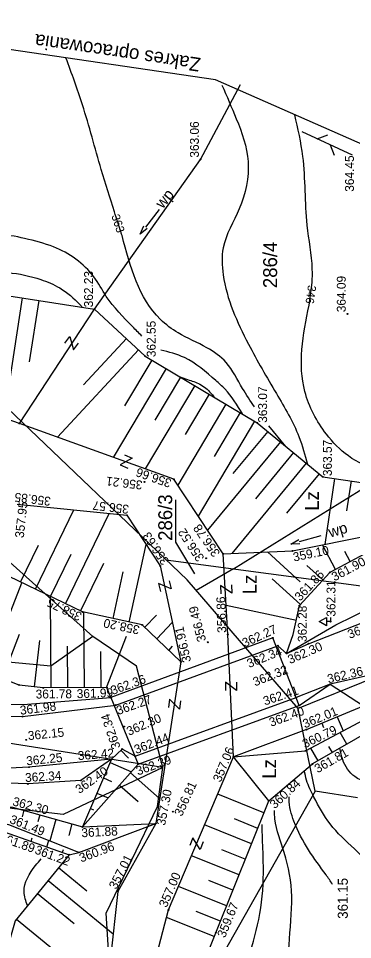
# Model space of a CAD drawing. Extents: x 4635329 to 4651863, y 5356628 to 5367582.
# Drawn here: x 4651193.1 to 4651223.2, y 5356669.9 to 5356752.8 of the extents above; entities that cross this region are included whole.
import ezdxf

# ---------------------------------------------------------------- set-up
doc = ezdxf.new("R2010")
doc.units = 0
for name, color, linetype in [('Level 1', 7, 'Continuous'), ('Level 12', 7, 'Continuous'), ('Level 20', 7, 'Continuous'), ('Level 24', 7, 'Continuous'), ('Level 29', 7, 'Continuous'), ('Level 32', 7, 'Continuous'), ('Level 36', 7, 'Continuous'), ('Level 4', 7, 'Continuous'), ('Level 44', 7, 'Continuous'), ('Level 45', 7, 'Continuous'), ('Level 46', 7, 'Continuous'), ('Level 47', 7, 'Continuous'), ('Level 48', 7, 'Continuous'), ('Level 5', 7, 'Continuous'), ('Level 50', 7, 'Continuous'), ('Level 51', 7, 'Continuous'), ('Level 53', 7, 'Continuous'), ('Level 6', 7, 'Continuous')]:
    doc.layers.add(name, color=color, linetype=linetype)

msp = doc.modelspace()

# ---------------------------------------------------------------- linework, layer by layer
at = {"layer": 'Level 1'}
for p, q in [((4651210.82, 5356747.317), (4651142.124, 5356757.357)), ((4651230.35, 5356738.707), (4651210.82, 5356747.317))]:
    msp.add_line(p, q, dxfattribs=at)
at = {"layer": 'Level 20'}
for p, q in [((4651219.185, 5356696.567), (4651225.385, 5356698.987)), ((4651201.855, 5356691.047), (4651216.435, 5356696.387)), ((4651217.225, 5356695.687), (4651219.185, 5356696.567))]:
    msp.add_line(p, q, dxfattribs=at)
for points in [[(4651122.765, 5356712.887), (4651146.685, 5356703.427), (4651159.565, 5356698.457), (4651170.205, 5356694.067), (4651178.895, 5356691.327), (4651182.663, 5356690.554), (4651185.995, 5356690.057), (4651193.465, 5356690.007), (4651201.855, 5356691.047)], [(4651201.455, 5356686.167), (4651194.035, 5356685.457), (4651185.485, 5356685.017), (4651181.21, 5356685.664), (4651178.315, 5356686.247), (4651168.145, 5356689.587), (4651157.765, 5356693.687), (4651144.895, 5356698.917), (4651120.155, 5356708.837)], [(4651311.985, 5356685.667), (4651297.855, 5356693.767), (4651287.285, 5356699.227), (4651283.015, 5356700.977), (4651280.145, 5356701.933), (4651275.335, 5356703.187), (4651271.856, 5356703.778), (4651268.065, 5356704.157), (4651257.665, 5356703.887), (4651250.625, 5356702.417), (4651229.275, 5356695.327), (4651226.835, 5356694.217), (4651221.145, 5356692.917), (4651218.085, 5356691.717)], [(4651221.145, 5356692.917), (4651224.155, 5356690.967), (4651229.698, 5356690.126), (4651238.165, 5356687.457), (4651245.645, 5356686.947), (4651253.435, 5356678.667)], [(4651203.595, 5356686.437), (4651218.085, 5356691.717)]]:
    msp.add_lwpolyline(points, dxfattribs=at)
at = {"layer": 'Level 24'}
for p, q in [((4651221.165, 5356698.557), (4651220.815, 5356698.557)), ((4651221.165, 5356698.932), (4651221.165, 5356698.557))]:
    msp.add_line(p, q, dxfattribs=at)
msp.add_lwpolyline([(4651220.815, 5356698.932), (4651220.815, 5356698.182), (4651220.165, 5356698.557)], close=True, dxfattribs=at)
at = {"layer": 'Level 29'}
msp.add_lwpolyline([(4651218.345, 5356691.007), (4651215.975, 5356697.087), (4651201.405, 5356691.717), (4651203.865, 5356685.737)], close=True, dxfattribs=at)
at = {"layer": 'Level 32'}
for p, q in [((4651223.161, 5356740.546), (4651218.621, 5356742.641)), ((4651219.983, 5356742.012), (4651220.921, 5356742.358)), ((4651221.157, 5356741.471), (4651221.503, 5356740.533))]:
    msp.add_line(p, q, dxfattribs=at)
at = {"layer": 'Level 4'}
for p, q in [((4651208.259, 5356702.31), (4651191.397, 5356718.379)), ((4651212.432, 5356703.313), (4651224.635, 5356710.859)), ((4651207.227, 5356709.519), (4651207.227, 5356705.702)), ((4651189.548, 5356706.371), (4651199.767, 5356697.217)), ((4651207.227, 5356705.702), (4651208.923, 5356702.854)), ((4651206.354, 5356704.126), (4651224.825, 5356701.657)), ((4651212.432, 5356703.313), (4651209.076, 5356701.364)), ((4651218.267, 5356690.729), (4651208.259, 5356702.31)), ((4651199.767, 5356697.217), (4651196.006, 5356694.549)), ((4651203.71, 5356694.549), (4651199.767, 5356697.217)), ((4651196.006, 5356694.549), (4651177.75, 5356696.277)), ((4651206.08, 5356685.424), (4651203.71, 5356694.549)), ((4651228.971, 5356695.066), (4651218.267, 5356690.729)), ((4651206.08, 5356685.424), (4651174.835, 5356690.307)), ((4651219.808, 5356683.279), (4651218.267, 5356690.729)), ((4651206.08, 5356685.424), (4651197.109, 5356681.204)), ((4651205.59, 5356681.906), (4651206.08, 5356685.424)), ((4651197.109, 5356681.204), (4651178.797, 5356683.326)), ((4651219.808, 5356683.279), (4651211.17, 5356668.081)), ((4651223.595, 5356682.687), (4651219.808, 5356683.279)), ((4651200.98, 5356672.325), (4651205.59, 5356681.906)), ((4651203.591, 5356632.939), (4651200.98, 5356672.325))]:
    msp.add_line(p, q, dxfattribs=at)
at = {"layer": 'Level 44'}
for centre in [(4651209.475, 5356740.157), (4651199.945, 5356726.687), (4651222.695, 5356726.247), (4651204.495, 5356722.447), (4651193.175, 5356716.387), (4651214.585, 5356716.447), (4651204.435, 5356711.127), (4651207.065, 5356711.367), (4651220.475, 5356711.587), (4651202.845, 5356708.137), (4651211.525, 5356704.647), (4651217.765, 5356704.917), (4651205.835, 5356703.577), (4651209.985, 5356704.257), (4651221.105, 5356702.987), (4651198.845, 5356699.427), (4651218.395, 5356700.007), (4651221.165, 5356698.557), (4651204.215, 5356698.267), (4651211.945, 5356697.397), (4651215.975, 5356697.087), (4651210.125, 5356696.697), (4651216.435, 5356696.387), (4651219.185, 5356696.567), (4651217.225, 5356695.687), (4651207.695, 5356694.927), (4651217.085, 5356693.927), (4651193.145, 5356692.847), (4651221.145, 5356692.917), (4651195.325, 5356692.587), (4651201.035, 5356692.627), (4651201.405, 5356691.717), (4651201.855, 5356691.047), (4651218.085, 5356691.717), (4651218.345, 5356691.007), (4651193.465, 5356690.007), (4651202.595, 5356689.107), (4651219.005, 5356688.837), (4651193.792, 5356687.909), (4651202.425, 5356687.087), (4651218.935, 5356686.927), (4651201.455, 5356686.167), (4651203.595, 5356686.437), (4651212.455, 5356686.387), (4651194.035, 5356685.457), (4651203.865, 5356685.737), (4651219.555, 5356685.747), (4651193.935, 5356683.947), (4651198.715, 5356684.257), (4651215.615, 5356682.427), (4651206.975, 5356681.447), (4651205.445, 5356680.397), (4651198.855, 5356680.077), (4651198.515, 5356677.787), (4651197.655, 5356677.577), (4651202.025, 5356674.277), (4651206.595, 5356672.607), (4651210.845, 5356670.557)]:
    msp.add_circle(centre, 0.04, dxfattribs=at)
at = {"layer": 'Level 46'}
for p, q in [((4651219.243, 5356727.032), (4651219.529, 5356729.059)), ((4651217.167, 5356714.317), (4651215.62, 5356716.158))]:
    msp.add_line(p, q, dxfattribs=at)
for points in [[(4651204.195, 5356724.252), (4651203.361, 5356725.098), (4651200.995, 5356727.826), (4651199.873, 5356729.585), (4651196.249, 5356732.275), (4651193.641, 5356733.033), (4651191.154, 5356733.306), (4651188.364, 5356732.275), (4651185.605, 5356732.093), (4651183.512, 5356732.548), (4651181.615, 5356733.242), (4651180.554, 5356740.7), (4651184.132, 5356743.489), (4651186.498, 5356745.338), (4651187.923, 5356747.43), (4651189.44, 5356750.442)], [(4651201.723, 5356735.433), (4651200.535, 5356739.239), (4651198.848, 5356745.072), (4651197.362, 5356749.284)], [(4651211.392, 5356746.839), (4651212.696, 5356743.807), (4651213.757, 5356739.957), (4651212.968, 5356735.712), (4651211.513, 5356732.196), (4651211.513, 5356729.77), (4651213.785, 5356723.537), (4651216.302, 5356719.08), (4651218.334, 5356715.2), (4651219.113, 5356712.711)], [(4651219.529, 5356729.059), (4651219.536, 5356730.286), (4651219.082, 5356734.227), (4651218.689, 5356740.425), (4651217.952, 5356744.173)], [(4651202.411, 5356733.299), (4651202.324, 5356733.569), (4651201.723, 5356735.433)], [(4651214.332, 5356717.879), (4651213.262, 5356719.537), (4651211.776, 5356721.872), (4651210.047, 5356723.206), (4651207.45, 5356724.535), (4651205.873, 5356725.748), (4651202.411, 5356733.299)], [(4651185.981, 5356729.569), (4651186.583, 5356729.429), (4651189.555, 5356729.762), (4651192.163, 5356729.944), (4651195.087, 5356729.339), (4651196.815, 5356728.581), (4651198.605, 5356727.096), (4651198.829, 5356726.859)], [(4651234.621, 5356711.14), (4651232.261, 5356711.494), (4651228.773, 5356712.252), (4651225.559, 5356712.282), (4651222.781, 5356713.461), (4651220.81, 5356715.431), (4651218.869, 5356719.251), (4651218.596, 5356723.041), (4651219.243, 5356727.032)], [(4651213.251, 5356717.24), (4651211.663, 5356719.494), (4651210.851, 5356720.247), (4651208.031, 5356722.309), (4651205.901, 5356722.997)], [(4651207.632, 5356720.582), (4651208.302, 5356720.339), (4651209.424, 5356719.915), (4651210.394, 5356719.127), (4651210.681, 5356718.769)], [(4651235.574, 5356680.782), (4651233.613, 5356682.904), (4651230.338, 5356685.268), (4651227.669, 5356685.026), (4651225.667, 5356684.177), (4651223.363, 5356684.601), (4651222.271, 5356686.117), (4651222.011, 5356687.156)], [(4651228.12, 5356672.269), (4651226.297, 5356674.945), (4651223.325, 5356678.098), (4651221.142, 5356680.341), (4651219.686, 5356682.766), (4651219.019, 5356684.282), (4651218.821, 5356685.129)], [(4651221.361, 5356674.907), (4651220.777, 5356675.758), (4651219.2, 5356678.001), (4651217.883, 5356680.579), (4651217.459, 5356682.58), (4651217.469, 5356682.777)], [(4651214.541, 5356635.926), (4651215.44, 5356637.377), (4651218.048, 5356641.682), (4651220.05, 5356646.351), (4651221.202, 5356650.595), (4651221.02, 5356654.294), (4651220.11, 5356658.417), (4651217.442, 5356667.027), (4651217.442, 5356669.452), (4651217.684, 5356673.818), (4651217.017, 5356677.759), (4651216.168, 5356680.79), (4651216.131, 5356681.56)], [(4651214.19, 5356661.051), (4651213.196, 5356664.419), (4651213.681, 5356667.815), (4651214.712, 5356671.756), (4651215.137, 5356675.94), (4651215.076, 5356678.426), (4651215.015, 5356680.305)], [(4651193.902, 5356672.991), (4651193.59, 5356674.238), (4651194.621, 5356676.602), (4651195.138, 5356677.203)]]:
    msp.add_spline(points, degree=3, dxfattribs=at)
at = {"layer": 'Level 48'}
for p, q in [((4651193.43, 5356727.693), (4651191.76, 5356716.874)), ((4651194.912, 5356727.464), (4651194.057, 5356721.921)), ((4651202.804, 5356724.023), (4651198.929, 5356719.865)), ((4651203.901, 5356723), (4651196.589, 5356715.153)), ((4651205.087, 5356722.095), (4651202.636, 5356717.974)), ((4651206.376, 5356721.328), (4651201.622, 5356713.334)), ((4651207.665, 5356720.562), (4651205.362, 5356716.688)), ((4651208.955, 5356719.795), (4651204.495, 5356712.296)), ((4651210.244, 5356719.028), (4651208.088, 5356715.403)), ((4651211.76, 5356718.127), (4651207.421, 5356710.83)), ((4651213.049, 5356717.36), (4651210.695, 5356713.402)), ((4651214.339, 5356716.594), (4651209.262, 5356708.057)), ((4651215.521, 5356715.675), (4651212.385, 5356711.875)), ((4651216.678, 5356714.72), (4651210.117, 5356706.769)), ((4651217.835, 5356713.766), (4651214.409, 5356709.614)), ((4651218.992, 5356712.811), (4651212.283, 5356704.68)), ((4651220.149, 5356711.856), (4651217.224, 5356708.312)), ((4651221.54, 5356711.43), (4651220.666, 5356705.501)), ((4651223.024, 5356711.211), (4651222.626, 5356708.513)), ((4651194.628, 5356701.462), (4651198.08, 5356708.615)), ((4651197.33, 5356700.158), (4651201.257, 5356708.296)), ((4651193.277, 5356702.114), (4651194.884, 5356705.444)), ((4651203.065, 5356698.515), (4651204.574, 5356705.5)), ((4651221.618, 5356703.257), (4651220.458, 5356705.459)), ((4651195.979, 5356700.81), (4651197.823, 5356704.633)), ((4651218.454, 5356702.127), (4651215.494, 5356704.819)), ((4651222.945, 5356703.957), (4651222.468, 5356704.862)), ((4651198.68, 5356699.506), (4651200.763, 5356703.822)), ((4651220.486, 5356702.306), (4651219.054, 5356703.608)), ((4651201.599, 5356698.832), (4651202.509, 5356703.046)), ((4651190.245, 5356693.976), (4651193.393, 5356702.058)), ((4651198.845, 5356699.427), (4651192.255, 5356702.607)), ((4651218.468, 5356700.087), (4651215.917, 5356702.407)), ((4651196.017, 5356692.592), (4651195.96, 5356700.819)), ((4651204.215, 5356698.267), (4651198.845, 5356699.427)), ((4651199.017, 5356692.613), (4651198.97, 5356699.4)), ((4651218.1, 5356698.647), (4651211.793, 5356700.014)), ((4651204.448, 5356698.043), (4651205.501, 5356699.14)), ((4651207.695, 5356694.927), (4651204.215, 5356698.267)), ((4651205.531, 5356697.004), (4651206.934, 5356698.466)), ((4651191.643, 5356693.432), (4651193.195, 5356697.418)), ((4651194.523, 5356692.683), (4651195.021, 5356696.857)), ((4651201.009, 5356692.627), (4651202.805, 5356697.238)), ((4651197.517, 5356692.602), (4651197.491, 5356696.348)), ((4651206.613, 5356695.966), (4651206.964, 5356696.331)), ((4651200.517, 5356692.623), (4651200.495, 5356695.849)), ((4651220.391, 5356689.41), (4651220.549, 5356689.028)), ((4651221.777, 5356689.984), (4651222.302, 5356688.715)), ((4651222.653, 5356687.524), (4651222.047, 5356688.58)), ((4651202.308, 5356686.976), (4651202.994, 5356686.252)), ((4651220.051, 5356686.031), (4651219.396, 5356687.172)), ((4651221.352, 5356686.778), (4651221.037, 5356687.327)), ((4651201.328, 5356685.868), (4651203.254, 5356685.046)), ((4651200.739, 5356684.489), (4651201.472, 5356684.176)), ((4651203.171, 5356684.953), (4651205.791, 5356682.633)), ((4651202.177, 5356683.83), (4651203.848, 5356682.35)), ((4651200.15, 5356683.109), (4651201.158, 5356682.679)), ((4651215.178, 5356681.339), (4651211.019, 5356683.01)), ((4651193.575, 5356681.577), (4651193.407, 5356680.985)), ((4651195.018, 5356681.167), (4651194.837, 5356680.529)), ((4651199.561, 5356681.73), (4651199.835, 5356681.612)), ((4651196.461, 5356680.757), (4651195.909, 5356678.812)), ((4651197.904, 5356680.347), (4651197.608, 5356679.304)), ((4651198.972, 5356680.35), (4651199.062, 5356680.312)), ((4651214.619, 5356679.947), (4651212.525, 5356680.789)), ((4651214.059, 5356678.556), (4651209.845, 5356680.249)), ((4651194.222, 5356678.784), (4651194.329, 5356679.088)), ((4651195.637, 5356678.286), (4651195.832, 5356678.842)), ((4651197.052, 5356677.789), (4651197.141, 5356678.041)), ((4651213.5, 5356677.164), (4651211.379, 5356678.016)), ((4651212.941, 5356675.772), (4651208.671, 5356677.488)), ((4651196.705, 5356676.416), (4651199.253, 5356674.33)), ((4651195.755, 5356675.255), (4651201.606, 5356670.466)), ((4651211.822, 5356672.988), (4651207.496, 5356674.727)), ((4651212.381, 5356674.38), (4651210.232, 5356675.244)), ((4651194.805, 5356674.095), (4651198.108, 5356671.391)), ((4651211.263, 5356671.597), (4651209.086, 5356672.471)), ((4651192.905, 5356671.773), (4651196.255, 5356669.031)), ((4651210.705, 5356670.204), (4651206.411, 5356671.913))]:
    msp.add_line(p, q, dxfattribs=at)
for points in [[(4651159.865, 5356744.577), (4651172.015, 5356735.297), (4651176.775, 5356730.907), (4651185.825, 5356728.867), (4651199.945, 5356726.687), (4651204.495, 5356722.447), (4651214.585, 5356716.447), (4651220.475, 5356711.587), (4651225.965, 5356710.777), (4651235.295, 5356710.407), (4651240.045, 5356721.267)], [(4651217.225, 5356695.687), (4651221.658, 5356698.264), (4651224.835, 5356699.83), (4651236.075, 5356706.167)], [(4651236.075, 5356706.167), (4651225.165, 5356705.127), (4651221.105, 5356702.987), (4651218.395, 5356700.007)], [(4651217.225, 5356695.687), (4651217.829, 5356697.397), (4651218.395, 5356700.007)], [(4651217.225, 5356695.687), (4651216.435, 5356696.387)], [(4651201.405, 5356691.717), (4651201.035, 5356692.627), (4651195.325, 5356692.587), (4651193.145, 5356692.847), (4651187.265, 5356695.137), (4651186.265, 5356691.127)], [(4651218.345, 5356691.007), (4651221.145, 5356692.917)], [(4651186.265, 5356691.127), (4651193.521, 5356691.081), (4651201.405, 5356691.717)], [(4651219.005, 5356688.837), (4651224.155, 5356690.967)], [(4651218.935, 5356686.927), (4651224.679, 5356689.977)], [(4651219.005, 5356688.837), (4651212.455, 5356686.387)], [(4651225.255, 5356689.017), (4651219.555, 5356685.747)], [(4651203.595, 5356686.437), (4651202.425, 5356687.087), (4651201.455, 5356686.167), (4651198.855, 5356680.077)], [(4651212.455, 5356686.387), (4651218.935, 5356686.927)], [(4651201.455, 5356686.167), (4651198.715, 5356684.257), (4651193.935, 5356683.947)], [(4651215.615, 5356682.427), (4651212.455, 5356686.387)], [(4651184.645, 5356682.547), (4651192.555, 5356681.867), (4651198.855, 5356680.077), (4651203.865, 5356685.737)], [(4651204.545, 5356634.907), (4651206.505, 5356647.167), (4651208.385, 5356664.377), (4651210.845, 5356670.557), (4651215.615, 5356682.427), (4651219.555, 5356685.747)], [(4651193.935, 5356683.947), (4651184.185, 5356684.287)], [(4651184.565, 5356682.391), (4651185.115, 5356681.597), (4651191.795, 5356679.637), (4651197.655, 5356677.577)], [(4651198.515, 5356677.787), (4651192.235, 5356680.257), (4651185.115, 5356681.597)], [(4651197.655, 5356677.577), (4651198.515, 5356677.787), (4651205.445, 5356680.397)], [(4651198.855, 5356680.077), (4651205.445, 5356680.397)], [(4651197.655, 5356677.577), (4651192.785, 5356671.627), (4651190.685, 5356664.357), (4651184.035, 5356649.037), (4651181.425, 5356636.777)]]:
    msp.add_lwpolyline(points, dxfattribs=at)
at = {"layer": 'Level 50'}
for p, q in [((4651209.475, 5356740.157), (4651213.084, 5356746.886)), ((4651199.945, 5356726.687), (4651209.475, 5356740.157)), ((4651205.757, 5356735.635), (4651204.524, 5356734.06)), ((4651204.031, 5356733.43), (4651204.367, 5356734.184)), ((4651204.681, 5356733.937), (4651204.031, 5356733.43)), ((4651193.175, 5356716.387), (4651199.945, 5356726.687)), ((4651193.175, 5356716.387), (4651171.415, 5356723.877)), ((4651207.065, 5356711.367), (4651193.175, 5356716.387)), ((4651211.525, 5356704.647), (4651207.065, 5356711.367)), ((4651192.985, 5356709.127), (4651202.845, 5356708.137)), ((4651202.845, 5356708.137), (4651205.835, 5356703.577)), ((4651217.765, 5356704.917), (4651225.615, 5356706.497)), ((4651220.298, 5356706.263), (4651218.368, 5356705.738)), ((4651217.596, 5356705.528), (4651218.316, 5356705.931)), ((4651218.42, 5356705.545), (4651217.596, 5356705.528)), ((4651211.525, 5356704.647), (4651217.765, 5356704.917)), ((4651211.945, 5356697.397), (4651211.525, 5356704.647)), ((4651205.835, 5356703.577), (4651207.695, 5356694.927)), ((4651212.455, 5356686.387), (4651211.945, 5356697.397)), ((4651207.695, 5356694.927), (4651205.445, 5356680.397)), ((4651206.595, 5356672.607), (4651212.455, 5356686.387)), ((4651205.445, 5356680.397), (4651202.025, 5356674.277)), ((4651202.025, 5356674.277), (4651201.145, 5356666.267)), ((4651204.725, 5356665.557), (4651206.595, 5356672.607))]:
    msp.add_line(p, q, dxfattribs=at)
at = {"layer": 'Level 53'}
for p, q in [((4651197.254, 5356723.621), (4651197.705, 5356724.221)), ((4651197.705, 5356724.221), (4651198.054, 5356723.021)), ((4651198.054, 5356723.021), (4651198.505, 5356723.621)), ((4651202.625, 5356713.567), (4651203.314, 5356713.27)), ((4651203.314, 5356713.27), (4651202.229, 5356712.649)), ((4651202.229, 5356712.649), (4651202.918, 5356712.352)), ((4651205.681, 5356701.984), (4651205.86, 5356701.255)), ((4651206.831, 5356701.494), (4651205.681, 5356701.984)), ((4651206.652, 5356702.222), (4651206.831, 5356701.494)), ((4651212.259, 5356701.851), (4651212.303, 5356701.103)), ((4651211.261, 5356701.793), (4651211.305, 5356701.044)), ((4651212.303, 5356701.103), (4651211.261, 5356701.793)), ((4651211.712, 5356693.115), (4651211.712, 5356692.365)), ((4651212.712, 5356692.365), (4651211.712, 5356693.115)), ((4651212.712, 5356693.115), (4651212.712, 5356692.365)), ((4651206.697, 5356691.573), (4651206.584, 5356690.832)), ((4651207.573, 5356690.681), (4651206.697, 5356691.573)), ((4651207.686, 5356691.423), (4651207.573, 5356690.681)), ((4651208.789, 5356679.103), (4651208.518, 5356678.403)), ((4651209.451, 5356678.043), (4651208.789, 5356679.103)), ((4651209.722, 5356678.742), (4651209.451, 5356678.043))]:
    msp.add_line(p, q, dxfattribs=at)

# ---------------------------------------------------------------- texts
at = {"layer": 'Level 12'}
for p in [(4651220.126, 5356708.531), (4651214.521, 5356701.018), (4651216.283, 5356684.413)]:
    msp.add_text('Lz', height=1.25, rotation=90, dxfattribs=at).set_placement(p)
at = {"layer": 'Level 36'}
msp.add_text('361.15', height=0.9, rotation=90, dxfattribs=at).set_placement((4651222.731, 5356671.804))
at = {"layer": 'Level 45'}
for s, rotation, p in [('363.06', 90, (4651209.325, 5356740.307)), ('364.45', 90, (4651223.282, 5356737.24)), ('362.23', 90, (4651199.795, 5356726.837)), ('364.09', 90, (4651222.545, 5356726.397)), ('362.55', 90, (4651205.436, 5356722.354)), ('363.07', 90, (4651215.465, 5356716.445)), ('363.57', 90, (4651221.295, 5356711.646)), ('356.66', 160.56142, (4651206.931, 5356711.333)), ('356.21', 173.34868, (4651204.287, 5356711.222)), ('356.85', 172.83323, (4651196.037, 5356709.758)), ('357.95', 83.66988, (4651193.559, 5356706.053)), ('356.57', 173.28613, (4651203.067, 5356709.042)), ('356.52', 123.25121, (4651209.854, 5356704.296)), ('356.78', 124.72106, (4651211.28, 5356704.727)), ('356.63', 124.04238, (4651206.697, 5356703.989)), ('359.10', 11.73764, (4651217.892, 5356703.951)), ('361.90', 28.00664, (4651221.538, 5356702.167)), ('361.86', 46.89071, (4651218.443, 5356700.35)), ('362.31', 90, (4651221.621, 5356698.995)), ('358.75', 154.30324, (4651198.87, 5356699.288)), ('356.86', 91.68305, (4651211.794, 5356697.549)), ('356.49', 104.38107, (4651209.989, 5356696.854)), ('362.28', 90, (4651219.035, 5356696.717)), ('358.20', 168.19379, (4651204.047, 5356698.165)), ('362.43', 21.4894, (4651222.901, 5356696.993)), ('356.91', 102.53305, (4651208.633, 5356694.977)), ('362.27', 24.45096, (4651213.448, 5356696.224)), ('362.34', 21.83369, (4651213.845, 5356694.37)), ('362.30', 23.51003, (4651217.536, 5356694.725)), ('362.32', 21.66194, (4651214.384, 5356692.718)), ('362.36', 13.40451, (4651220.99, 5356692.991)), ('362.36', 19.992, (4651201.563, 5356691.946)), ('361.78', 0.41398, (4651194.637, 5356691.63)), ('361.99', 1.73221, (4651198.344, 5356691.661)), ('362.27', 19.265, (4651202.063, 5356690.144)), ('362.41', 18.2847, (4651215.269, 5356690.997)), ('361.98', 6.96967, (4651193.274, 5356690.165)), ('362.34', 108.57274, (4651202.285, 5356687.241)), ('362.30', 23.53157, (4651203.032, 5356688.268)), ('362.40', 20.19151, (4651215.824, 5356689.075)), ('362.01', 22.58021, (4651218.874, 5356688.938)), ('362.15', 5.79384, (4651193.978, 5356687.883)), ('360.79', 25.10525, (4651218.871, 5356687.144)), ('362.44', 21.35279, (4651203.685, 5356686.627)), ('362.42', 4.52498, (4651198.456, 5356686.082)), ('357.06', 67.36823, (4651211.287, 5356684.044)), ('361.81', 29.84326, (4651220.02, 5356684.897)), ('362.25', 5.79384, (4651193.826, 5356685.613)), ('362.39', 19.76116, (4651203.844, 5356684.698)), ('362.40', 35.04555, (4651198.564, 5356683.026)), ('362.34', 3.6512, (4651193.708, 5356684.109)), ('356.81', 65.17557, (4651207.79, 5356680.963)), ('360.84', 43.02841, (4651216.157, 5356681.659)), ('357.30', 78.93676, (4651206.281, 5356680.154)), ('362.30', 344.81689, (4651192.498, 5356682.028)), ('361.49', 338.26852, (4651192.224, 5356680.454)), ('361.89', 340.45828, (4651191.313, 5356678.824)), ('361.88', 2.89033, (4651198.772, 5356679.145)), ('360.96', 20.48774, (4651198.737, 5356676.87)), ('361.22', 339.35153, (4651194.486, 5356677.706)), ('357.01', 62.65723, (4651201.888, 5356674.401)), ('357.00', 66.50612, (4651206.422, 5356672.762)), ('359.67', 67.57867, (4651211.673, 5356670.039))]:
    msp.add_text(s, height=0.8, rotation=rotation, dxfattribs=at).set_placement(p)
at = {"layer": 'Level 47'}
for s, rotation, p in [('363', 287.9013, (4651201.445, 5356735.071)), ('346', 261.67301, (4651219.159, 5356728.874))]:
    msp.add_text(s, height=0.75, rotation=rotation, dxfattribs=at).set_placement(p)
at = {"layer": 'Level 5'}
for s, p in [('286/4', (4651216.365, 5356728.567)), ('286/3', (4651206.923, 5356705.823))]:
    msp.add_text(s, height=1.25, rotation=90, dxfattribs=at).set_placement(p)
at = {"layer": 'Level 51'}
for rotation, p in [(50.57006, (4651206.071, 5356735.649)), (16.75948, (4651221.154, 5356706.099))]:
    msp.add_text('wp', height=1, rotation=rotation, dxfattribs=at).set_placement(p)
at = {"layer": 'Level 6'}
msp.add_text('Zakres opracowania', height=1.25, rotation=171.68502, dxfattribs=at).set_placement((4651209.547, 5356749.272))

doc.saveas('drawing.dxf')
